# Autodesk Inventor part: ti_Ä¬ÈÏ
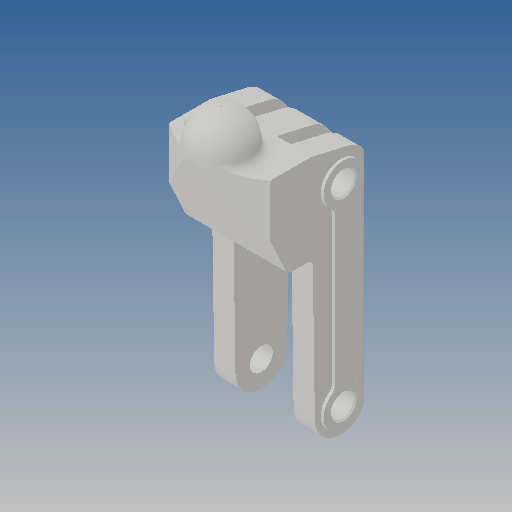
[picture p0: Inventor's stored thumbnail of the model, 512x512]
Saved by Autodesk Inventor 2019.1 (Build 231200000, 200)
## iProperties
Created: 2012-10
Part Number: ti_Ä¬ÈÏ
Material: Ogólny
Document SubType Name: Modeling
Designer: CADENGINEERING4
Density: 1 g/cm^3
Appearance: Domyślna
Author: CADENGINEERING4
Revision Number: ÈÎºÎ
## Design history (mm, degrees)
feature "NONE"
node "Bryła1"
